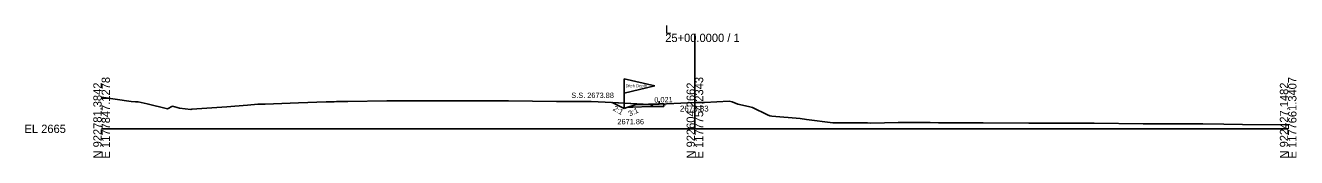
# Model space of a CAD drawing. Extents: x -26 to 1403, y -10 to 9563.
# Drawn here: x 974.3 to 1402.8, y 4990.3 to 5034.9 of the extents above; entities that cross this region are included whole.
import ezdxf

# ---------------------------------------------------------------- set-up
doc = ezdxf.new("R2010")
doc.units = 0
for name, color, linetype in [('Exist Cross Section Cell', 7, 'Continuous'), ('Exist XS Center Line Elevation Label', 7, 'Continuous'), ('Exist XS Ground Line', 7, 'Continuous'), ('Prop XS Ditch Slope Text', 7, 'Continuous'), ('Prop XS Ditch Standard Text', 7, 'Continuous'), ('Prop XS Dump Level', 7, 'Continuous'), ('Prop XS Earthwork Shape', 7, 'Continuous'), ('Prop XS EOT Tick Mark', 7, 'Continuous'), ('Prop XS Finish Grade', 7, 'Continuous'), ('Prop XS Finish Grade Earthwork', 7, 'Continuous'), ('Prop XS Finish Grade Pavement', 7, 'Continuous'), ('Prop XS Pvmt Edge Slope', 7, 'Continuous'), ('Prop XS SE Text', 7, 'Continuous'), ('Prop XS Shoulder Borrow Shape', 7, 'Continuous'), ('Prop XS Side Slope Text', 7, 'Continuous'), ('Prop XS SS Elevation Text', 7, 'Continuous'), ('Prop XS Subgrade Earthwork', 7, 'Continuous')]:
    doc.layers.add(name, color=color, linetype=linetype)

msp = doc.modelspace()

# ---------------------------------------------------------------- linework, layer by layer
at = {"layer": 'Exist Cross Section Cell'}
for p, q in [((1200, 5000), (1200, 5032.07)), ((1000, 5000), (1200, 5000)), ((1200, 5000), (1400, 5000))]:
    msp.add_line(p, q, dxfattribs=at)
at = {"layer": 'Exist XS Ground Line'}
for p, q in [((1000, 5010.69), (1009.95, 5009.2)), ((1009.95, 5009.2), (1011.47, 5009.1)), ((1011.47, 5009.1), (1012.37, 5009.08)), ((1012.37, 5009.08), (1015.3, 5008.48)), ((1015.3, 5008.48), (1022.21, 5006.73)), ((1022.21, 5006.73), (1023.94, 5007.61)), ((1023.94, 5007.61), (1026.24, 5006.96)), ((1026.24, 5006.96), (1030.12, 5006.57)), ((1030.12, 5006.57), (1030.43, 5006.59)), ((1030.43, 5006.59), (1042.24, 5007.43)), ((1042.24, 5007.43), (1044.89, 5007.64)), ((1044.89, 5007.64), (1049.17, 5007.97)), ((1049.17, 5007.97), (1052.71, 5008.27)), ((1052.71, 5008.27), (1053.14, 5008.3)), ((1053.14, 5008.3), (1053.75, 5008.33)), ((1053.75, 5008.33), (1054.21, 5008.34)), ((1054.21, 5008.34), (1055.11, 5008.37)), ((1055.11, 5008.37), (1066.35, 5008.78)), ((1066.35, 5008.78), (1075.71, 5009.05)), ((1075.71, 5009.05), (1078.39, 5009.14)), ((1078.39, 5009.14), (1079.2, 5009.19)), ((1079.2, 5009.19), (1079.74, 5009.22)), ((1079.74, 5009.22), (1082.98, 5009.26)), ((1082.98, 5009.26), (1096.17, 5009.39)), ((1096.17, 5009.39), (1105.52, 5009.48)), ((1105.52, 5009.48), (1113.43, 5009.49)), ((1113.43, 5009.49), (1123.9, 5009.46)), ((1123.9, 5009.46), (1137.17, 5009.41)), ((1137.17, 5009.41), (1153.37, 5009.24)), ((1153.37, 5009.24), (1165.03, 5009.18)), ((1165.03, 5009.18), (1169.7, 5009.02)), ((1169.7, 5009.02), (1182.55, 5008.29)), ((1182.55, 5008.29), (1184.11, 5008.22)), ((1184.11, 5008.22), (1184.86, 5008.23)), ((1184.86, 5008.23), (1187.97, 5008.36)), ((1187.97, 5008.36), (1200.19, 5008.83)), ((1200.19, 5008.83), (1203.26, 5008.84)), ((1203.26, 5008.84), (1211.53, 5009.32)), ((1211.53, 5009.32), (1212.6, 5009.06)), ((1212.6, 5009.06), (1214.46, 5008.35)), ((1214.46, 5008.35), (1218.06, 5007.49)), ((1218.06, 5007.49), (1219.47, 5007.19)), ((1219.47, 5007.19), (1224.49, 5004.72)), ((1224.49, 5004.72), (1225.26, 5004.33)), ((1225.26, 5004.33), (1225.95, 5004.31)), ((1225.95, 5004.31), (1235.44, 5003.5)), ((1235.44, 5003.5), (1237.57, 5003.17)), ((1237.57, 5003.17), (1246.48, 5002.06)), ((1246.48, 5002.06), (1251.9, 5002)), ((1251.9, 5002), (1252.45, 5001.99)), ((1252.45, 5001.99), (1258.16, 5001.99)), ((1258.16, 5001.99), (1259.29, 5001.95)), ((1259.29, 5001.95), (1268.49, 5002.18)), ((1268.49, 5002.18), (1279.37, 5002.08)), ((1279.37, 5002.08), (1282.17, 5002.07)), ((1282.17, 5002.07), (1285.98, 5002.01)), ((1285.98, 5002.01), (1297.19, 5002)), ((1297.19, 5002), (1312.55, 5001.94)), ((1312.55, 5001.94), (1324.16, 5001.92)), ((1324.16, 5001.92), (1334.6, 5001.86)), ((1334.6, 5001.86), (1351.13, 5001.72)), ((1351.13, 5001.72), (1371.26, 5001.65)), ((1371.26, 5001.65), (1378.36, 5001.59)), ((1378.36, 5001.59), (1384.66, 5001.5)), ((1384.66, 5001.5), (1399.06, 5001.31)), ((1399.06, 5001.31), (1400, 5001.3))]:
    msp.add_line(p, q, dxfattribs=at)
at = {"layer": 'Prop XS Dump Level'}
for p, q in [((1176.18, 5012.06), (1176.18, 5016.86)), ((1176.18, 5016.86), (1186.48, 5014.46)), ((1186.48, 5014.46), (1176.18, 5012.06)), ((1176.18, 5006.86), (1176.18, 5012.06)), ((1185.92, 5008.34), (1189.54, 5008.42)), ((1189.54, 5008.42), (1187.92, 5008.38))]:
    msp.add_line(p, q, dxfattribs=at)
at = {"layer": 'Prop XS Earthwork Shape'}
for p, q in [((1172.14, 5008.88), (1182.55, 5008.29)), ((1176.18, 5006.86), (1172.14, 5008.88)), ((1177.11, 5007.17), (1176.18, 5006.86)), ((1179.05, 5007.25), (1177.11, 5007.17)), ((1185.07, 5007.49), (1179.05, 5007.25)), ((1183.49, 5008.25), (1182.55, 5008.29)), ((1182.55, 5008.29), (1184.11, 5008.22)), ((1184.34, 5008.28), (1183.49, 5008.25)), ((1183.49, 5008.25), (1184.11, 5008.22)), ((1184.11, 5008.22), (1184.86, 5008.23)), ((1184.11, 5008.22), (1184.86, 5008.23)), ((1185.92, 5008.34), (1184.34, 5008.28)), ((1184.86, 5008.23), (1187.97, 5008.36)), ((1184.86, 5008.23), (1185.84, 5008.27)), ((1187.92, 5007.55), (1185.07, 5007.49)), ((1187.97, 5008.36), (1185.84, 5008.27)), ((1185.84, 5008.27), (1185.92, 5008.34)), ((1189.54, 5007.58), (1187.92, 5007.55)), ((1187.97, 5008.36), (1189.54, 5008.42)), ((1189.54, 5008.42), (1189.54, 5007.58))]:
    msp.add_line(p, q, dxfattribs=at)
at = {"layer": 'Prop XS EOT Tick Mark'}
msp.add_line((1187.92, 5008.38), (1187.92, 5009.38), dxfattribs=at)
at = {"layer": 'Prop XS Finish Grade'}
msp.add_line((1185.92, 5008.34), (1184.34, 5008.28), dxfattribs=at)
at = {"layer": 'Prop XS Finish Grade Earthwork'}
for p, q in [((1176.18, 5006.86), (1172.14, 5008.88)), ((1177.11, 5007.17), (1176.18, 5006.86)), ((1179.9, 5008.1), (1177.11, 5007.17)), ((1184.34, 5008.28), (1179.9, 5008.1))]:
    msp.add_line(p, q, dxfattribs=at)
at = {"layer": 'Prop XS Finish Grade Pavement'}
msp.add_line((1185.92, 5008.34), (1189.54, 5008.42), dxfattribs=at)
at = {"layer": 'Prop XS Pvmt Edge Slope'}
msp.add_line((1185.92, 5008.34), (1185.07, 5007.49), dxfattribs=at)
at = {"layer": 'Prop XS Shoulder Borrow Shape'}
for p, q in [((1179.9, 5008.1), (1177.11, 5007.17)), ((1177.11, 5007.17), (1179.05, 5007.25)), ((1179.05, 5007.25), (1185.07, 5007.49)), ((1183.49, 5008.25), (1179.9, 5008.1)), ((1184.11, 5008.22), (1183.49, 5008.25)), ((1184.86, 5008.23), (1184.11, 5008.22)), ((1185.84, 5008.27), (1184.86, 5008.23)), ((1185.07, 5007.49), (1185.84, 5008.27))]:
    msp.add_line(p, q, dxfattribs=at)
at = {"layer": 'Prop XS Subgrade Earthwork'}
for p, q in [((1179.05, 5007.25), (1177.11, 5007.17)), ((1185.07, 5007.49), (1179.05, 5007.25)), ((1187.92, 5007.55), (1185.07, 5007.49)), ((1189.54, 5007.58), (1187.92, 5007.55)), ((1189.54, 5007.58), (1189.54, 5008.42))]:
    msp.add_line(p, q, dxfattribs=at)

# ---------------------------------------------------------------- texts
at = {"layer": 'Exist Cross Section Cell'}
for s, p in [('25+00.0000 / 1', (1190, 5029.27)), ('L', (1190, 5032.07)), ('EL 2665', (974, 4998.6))]:
    msp.add_text(s, height=2.8, dxfattribs=at).set_placement(p)
for s, p in [('N 922781.3842', (1000, 4990)), ('E 1177847.1278', (1002.8, 4990)), ('N 922604.2662', (1200, 4990)), ('E 1177754.2343', (1202.8, 4990)), ('N 922427.1482', (1400, 4990)), ('E 1177661.3407', (1402.8, 4990))]:
    msp.add_text(s, height=2.8, rotation=90, dxfattribs=at).set_placement(p)
at = {"layer": 'Exist XS Center Line Elevation Label'}
msp.add_text('2673.83', height=2, dxfattribs=at).set_placement((1194.96, 5005.83))
at = {"layer": 'Prop XS Ditch Slope Text'}
msp.add_text('3:1', height=1.8, rotation=24.3948, dxfattribs=at).set_placement((1178.05, 5004.18))
at = {"layer": 'Prop XS Ditch Standard Text'}
msp.add_text('2671.86', height=1.8, dxfattribs=at).set_placement((1173.87, 5001.53))
at = {"layer": 'Prop XS Dump Level'}
for s, height, p in [('Ditch Depth', 1, (1176.62, 5014.03)), ('Case1', 0.04, (1179.92, 5007.7)), ('Eop', 0.3, (1189.54, 5007.97))]:
    msp.add_text(s, height=height, dxfattribs=at).set_placement(p)
at = {"layer": 'Prop XS SE Text'}
msp.add_text('0.021', height=1.8, rotation=1.2002, dxfattribs=at).set_placement((1186.33, 5008.85))
at = {"layer": 'Prop XS Side Slope Text'}
msp.add_text('2:1', height=1.8, rotation=330.0183, dxfattribs=at).set_placement((1172.22, 5006.36))
at = {"layer": 'Prop XS SS Elevation Text'}
msp.add_text('S.S. 2673.88', height=1.8, dxfattribs=at).set_placement((1158.33, 5010.4))

doc.saveas('drawing.dxf')
